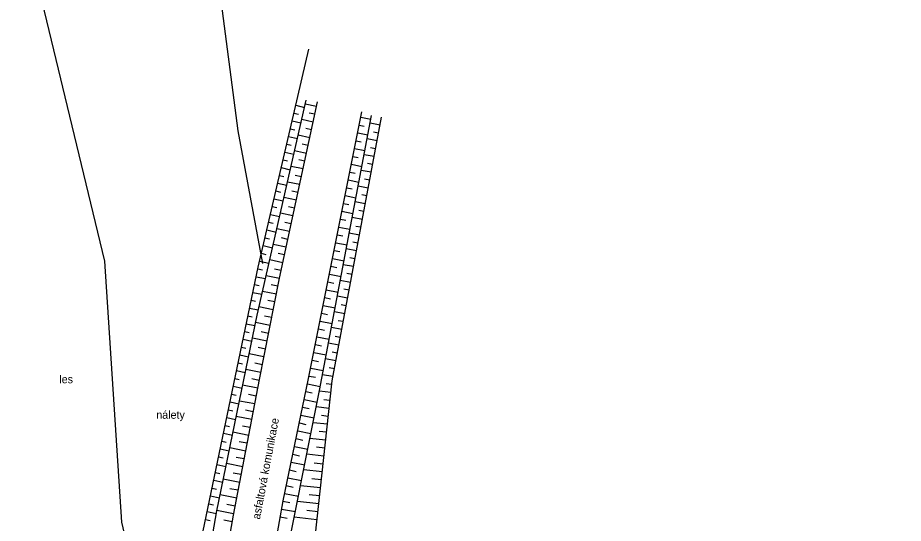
# Model space of a CAD drawing. Extents: x -762483 to -761175, y -1154655 to -1152452.
# Drawn here: x -761535.1 to -761452.1, y -1153499 to -1153451.6 of the extents above; entities that cross this region are included whole.
import ezdxf

# ---------------------------------------------------------------- set-up
doc = ezdxf.new("R2010")
doc.units = 0
for name, color, linetype in [('POMOC_POPIS', 7, 'Continuous'), ('ROZHRANÍ_PLOCH', 7, 'Continuous'), ('VÝŠKOPIS', 7, 'Continuous'), ('ZELEŇ', 7, 'Continuous')]:
    doc.layers.add(name, color=color, linetype=linetype)

msp = doc.modelspace()

# ---------------------------------------------------------------- linework, layer by layer
at = {"layer": 'ROZHRANÍ_PLOCH'}
for points in [[(-761473.21, -1153684.07), (-761469.46, -1153679.5), (-761466.97, -1153675.46), (-761465.27, -1153671.92), (-761464.53, -1153668.61), (-761464.73, -1153664.68), (-761466, -1153658.71), (-761468.55, -1153651.77), (-761473.7, -1153641.76), (-761483.81, -1153624.91), (-761489.13, -1153616.22), (-761501.02, -1153596.18), (-761505.16, -1153588.62), (-761508.76, -1153581.79), (-761515.86, -1153566.65), (-761518.43, -1153558.82), (-761520.62, -1153549.31), (-761520.92, -1153543.45), (-761519.67, -1153527.09), (-761518.4, -1153518.01), (-761514.9, -1153498.24), (-761512.46, -1153485.54), (-761510.57, -1153476.01), (-761507.02, -1153459.49)], [(-761452.11, -1153680.09), (-761455.06, -1153677.36), (-761457.46, -1153672.86), (-761459.23, -1153668.13), (-761461.75, -1153656.48), (-761464.72, -1153649.83), (-761470.08, -1153639.37), (-761481.24, -1153620.57), (-761493.92, -1153599.29), (-761502.78, -1153583.29), (-761511.19, -1153565.87), (-761514.81, -1153554.8), (-761515.74, -1153549.15), (-761516.42, -1153543.11), (-761515.79, -1153528.81), (-761514.01, -1153518.23), (-761510.25, -1153496.92), (-761507.85, -1153485.44), (-761506.02, -1153476.2), (-761502.85, -1153460.41)]]:
    msp.add_lwpolyline(points, dxfattribs=at)
at = {"layer": 'VÝŠKOPIS'}
for p, q in [((-761509.057, -1153459.81), (-761508.235, -1153460.002)), ((-761507.111, -1153459.915), (-761508.164, -1153459.689)), ((-761509.398, -1153461.271), (-761508.569, -1153461.464)), ((-761509.227, -1153460.541), (-761508.815, -1153460.637)), ((-761507.427, -1153461.382), (-761508.498, -1153461.152)), ((-761507.269, -1153460.649), (-761507.8, -1153460.534)), ((-761502.954, -1153460.928), (-761502.027, -1153461.114)), ((-761509.568, -1153462.002), (-761509.152, -1153462.098)), ((-761507.584, -1153462.115), (-761508.124, -1153461.999)), ((-761503.102, -1153461.663), (-761502.634, -1153461.757)), ((-761501.159, -1153461.669), (-761502.098, -1153461.493)), ((-761509.738, -1153462.732), (-761508.902, -1153462.926)), ((-761507.742, -1153462.848), (-761508.831, -1153462.614)), ((-761503.249, -1153462.399), (-761502.305, -1153462.588)), ((-761501.297, -1153462.407), (-761501.767, -1153462.319)), ((-761509.908, -1153463.462), (-761509.489, -1153463.56)), ((-761507.899, -1153463.582), (-761508.449, -1153463.464)), ((-761503.397, -1153463.134), (-761502.921, -1153463.23)), ((-761501.435, -1153463.144), (-761502.377, -1153462.967)), ((-761501.573, -1153463.881), (-761502.044, -1153463.793)), ((-761510.078, -1153464.193), (-761509.236, -1153464.389)), ((-761508.057, -1153464.315), (-761509.165, -1153464.077)), ((-761503.692, -1153464.605), (-761503.207, -1153464.702)), ((-761503.545, -1153463.869), (-761502.583, -1153464.062)), ((-761501.711, -1153464.618), (-761502.655, -1153464.441)), ((-761510.248, -1153464.923), (-761509.825, -1153465.022)), ((-761508.214, -1153465.048), (-761508.773, -1153464.928)), ((-761503.84, -1153465.34), (-761502.862, -1153465.537)), ((-761501.849, -1153465.355), (-761502.321, -1153465.267)), ((-761510.418, -1153465.654), (-761509.57, -1153465.851)), ((-761508.372, -1153465.781), (-761509.498, -1153465.539)), ((-761503.987, -1153466.075), (-761503.494, -1153466.175)), ((-761501.987, -1153466.093), (-761502.933, -1153465.915)), ((-761510.758, -1153467.115), (-761509.903, -1153467.314)), ((-761510.588, -1153466.384), (-761510.162, -1153466.483)), ((-761508.687, -1153467.248), (-761509.832, -1153467.002)), ((-761508.53, -1153466.515), (-761509.097, -1153466.393)), ((-761504.135, -1153466.811), (-761503.14, -1153467.011)), ((-761502.125, -1153466.83), (-761502.599, -1153466.741)), ((-761510.928, -1153467.845), (-761510.499, -1153467.945)), ((-761508.845, -1153467.981), (-761509.422, -1153467.857)), ((-761504.283, -1153467.546), (-761503.781, -1153467.647)), ((-761502.263, -1153467.567), (-761503.211, -1153467.389)), ((-761511.099, -1153468.576), (-761510.237, -1153468.776)), ((-761509.002, -1153468.714), (-761510.165, -1153468.464)), ((-761504.43, -1153468.281), (-761503.418, -1153468.485)), ((-761502.401, -1153468.304), (-761502.876, -1153468.215)), ((-761511.269, -1153469.306), (-761510.836, -1153469.407)), ((-761509.16, -1153469.448), (-761509.746, -1153469.322)), ((-761504.578, -1153469.017), (-761504.068, -1153469.119)), ((-761502.539, -1153469.041), (-761503.49, -1153468.863)), ((-761511.439, -1153470.037), (-761510.57, -1153470.239)), ((-761509.317, -1153470.181), (-761510.499, -1153469.927)), ((-761504.726, -1153469.752), (-761503.696, -1153469.959)), ((-761502.815, -1153470.516), (-761503.768, -1153470.337)), ((-761502.677, -1153469.778), (-761503.153, -1153469.689)), ((-761511.609, -1153470.767), (-761511.173, -1153470.868)), ((-761509.475, -1153470.914), (-761510.07, -1153470.786)), ((-761505.021, -1153471.223), (-761503.975, -1153471.433)), ((-761504.873, -1153470.487), (-761504.354, -1153470.592)), ((-761502.953, -1153471.253), (-761503.43, -1153471.164)), ((-761511.779, -1153471.497), (-761510.904, -1153471.701)), ((-761509.633, -1153471.647), (-761510.833, -1153471.39)), ((-761505.168, -1153471.958), (-761504.641, -1153472.064)), ((-761503.092, -1153471.99), (-761504.046, -1153471.811)), ((-761511.949, -1153472.228), (-761511.51, -1153472.33)), ((-761509.948, -1153473.114), (-761511.166, -1153472.852)), ((-761509.79, -1153472.381), (-761510.395, -1153472.251)), ((-761505.316, -1153472.693), (-761504.253, -1153472.907)), ((-761503.23, -1153472.727), (-761503.707, -1153472.638)), ((-761512.289, -1153473.689), (-761511.847, -1153473.792)), ((-761512.119, -1153472.958), (-761511.237, -1153473.164)), ((-761510.105, -1153473.847), (-761510.719, -1153473.715)), ((-761505.464, -1153473.429), (-761504.928, -1153473.536)), ((-761503.368, -1153473.464), (-761504.324, -1153473.285)), ((-761512.459, -1153474.419), (-761511.571, -1153474.626)), ((-761510.263, -1153474.58), (-761511.5, -1153474.315)), ((-761505.611, -1153474.164), (-761504.531, -1153474.381)), ((-761503.506, -1153474.202), (-761503.985, -1153474.112)), ((-761512.625, -1153475.151), (-761512.179, -1153475.243)), ((-761510.42, -1153475.314), (-761511.043, -1153475.18)), ((-761505.759, -1153474.899), (-761505.215, -1153475.009)), ((-761503.644, -1153474.939), (-761504.602, -1153474.759)), ((-761512.778, -1153475.885), (-761511.899, -1153476.067)), ((-761510.577, -1153476.047), (-761511.838, -1153475.797)), ((-761505.907, -1153475.635), (-761504.809, -1153475.855)), ((-761503.92, -1153476.413), (-761504.881, -1153476.233)), ((-761503.782, -1153475.676), (-761504.262, -1153475.586)), ((-761512.931, -1153476.619), (-761512.498, -1153476.709)), ((-761510.723, -1153476.783), (-761511.364, -1153476.656)), ((-761506.054, -1153476.37), (-761505.501, -1153476.48)), ((-761504.058, -1153477.15), (-761504.539, -1153477.06)), ((-761513.083, -1153477.354), (-761512.233, -1153477.53)), ((-761510.869, -1153477.518), (-761512.171, -1153477.26)), ((-761506.345, -1153477.842), (-761505.786, -1153477.952)), ((-761506.199, -1153477.106), (-761505.087, -1153477.326)), ((-761504.196, -1153477.887), (-761505.159, -1153477.707)), ((-761513.236, -1153478.088), (-761512.818, -1153478.175)), ((-761511.161, -1153478.99), (-761512.505, -1153478.723)), ((-761511.015, -1153478.254), (-761511.677, -1153478.123)), ((-761506.491, -1153478.577), (-761505.365, -1153478.8)), ((-761504.334, -1153478.625), (-761504.816, -1153478.534)), ((-761513.541, -1153479.557), (-761513.135, -1153479.641)), ((-761513.388, -1153478.822), (-761512.567, -1153478.993)), ((-761506.637, -1153479.313), (-761506.07, -1153479.425)), ((-761504.472, -1153479.362), (-761505.437, -1153479.181)), ((-761513.693, -1153480.291), (-761512.88, -1153480.46)), ((-761511.453, -1153480.461), (-761512.824, -1153480.189)), ((-761511.307, -1153479.725), (-761511.989, -1153479.59)), ((-761506.782, -1153480.049), (-761505.643, -1153480.274)), ((-761504.61, -1153480.099), (-761505.093, -1153480.009)), ((-761513.846, -1153481.025), (-761513.439, -1153481.11)), ((-761511.599, -1153481.197), (-761512.287, -1153481.06)), ((-761506.928, -1153480.784), (-761506.355, -1153480.898)), ((-761504.748, -1153480.836), (-761505.715, -1153480.655)), ((-761513.999, -1153481.759), (-761513.182, -1153481.929)), ((-761511.745, -1153481.933), (-761513.127, -1153481.658)), ((-761507.074, -1153481.52), (-761505.922, -1153481.748)), ((-761504.886, -1153481.573), (-761505.37, -1153481.483)), ((-761514.151, -1153482.494), (-761513.742, -1153482.579)), ((-761511.89, -1153482.668), (-761512.584, -1153482.531)), ((-761507.219, -1153482.256), (-761506.64, -1153482.371)), ((-761505.025, -1153482.311), (-761505.994, -1153482.129)), ((-761514.304, -1153483.228), (-761513.485, -1153483.398)), ((-761512.036, -1153483.404), (-761513.429, -1153483.128)), ((-761507.365, -1153482.992), (-761506.2, -1153483.222)), ((-761505.301, -1153483.785), (-761506.272, -1153483.603)), ((-761505.163, -1153483.048), (-761505.648, -1153482.957)), ((-761514.456, -1153483.962), (-761514.046, -1153484.048)), ((-761512.182, -1153484.14), (-761512.881, -1153484.001)), ((-761507.656, -1153484.463), (-761506.478, -1153484.696)), ((-761507.511, -1153483.727), (-761506.925, -1153483.843)), ((-761505.439, -1153484.522), (-761505.925, -1153484.431)), ((-761514.609, -1153484.697), (-761513.788, -1153484.867)), ((-761512.328, -1153484.875), (-761513.732, -1153484.597)), ((-761507.802, -1153485.199), (-761507.21, -1153485.316)), ((-761505.577, -1153485.259), (-761506.55, -1153485.077)), ((-761514.914, -1153486.165), (-761514.09, -1153486.336)), ((-761514.761, -1153485.431), (-761514.35, -1153485.516)), ((-761512.615, -1153486.347), (-761514.036, -1153486.074)), ((-761512.474, -1153485.611), (-761513.179, -1153485.475)), ((-761507.953, -1153485.933), (-761506.759, -1153486.183)), ((-761505.688, -1153486), (-761506.196, -1153485.945)), ((-761515.066, -1153486.9), (-761514.654, -1153486.985)), ((-761512.757, -1153487.084), (-761513.472, -1153486.947)), ((-761508.107, -1153486.667), (-761507.504, -1153486.793)), ((-761505.769, -1153486.746), (-761506.844, -1153486.629)), ((-761515.219, -1153487.634), (-761514.393, -1153487.806)), ((-761512.898, -1153487.821), (-761514.339, -1153487.544)), ((-761508.26, -1153487.402), (-761507.048, -1153487.655)), ((-761505.851, -1153487.492), (-761506.421, -1153487.429)), ((-761515.372, -1153488.368), (-761514.958, -1153488.454)), ((-761513.04, -1153488.557), (-761513.765, -1153488.418)), ((-761508.414, -1153488.136), (-761507.804, -1153488.263)), ((-761505.932, -1153488.237), (-761507.138, -1153488.106)), ((-761515.524, -1153489.103), (-761514.696, -1153489.275)), ((-761513.181, -1153489.294), (-761514.642, -1153489.013)), ((-761508.567, -1153488.87), (-761507.341, -1153489.126)), ((-761506.013, -1153488.983), (-761506.649, -1153488.913)), ((-761515.677, -1153489.837), (-761515.262, -1153489.923)), ((-761513.323, -1153490.03), (-761514.058, -1153489.889)), ((-761508.874, -1153490.338), (-761507.634, -1153490.597)), ((-761508.721, -1153489.604), (-761508.104, -1153489.733)), ((-761506.095, -1153489.728), (-761507.432, -1153489.583)), ((-761515.829, -1153490.571), (-761514.998, -1153490.744)), ((-761513.464, -1153490.767), (-761514.944, -1153490.482)), ((-761509.027, -1153491.072), (-761508.404, -1153491.203)), ((-761506.257, -1153491.219), (-761507.726, -1153491.059)), ((-761506.176, -1153490.474), (-761506.878, -1153490.397)), ((-761515.982, -1153491.306), (-761515.566, -1153491.392)), ((-761513.747, -1153492.24), (-761515.247, -1153491.952)), ((-761513.606, -1153491.503), (-761514.351, -1153491.36)), ((-761509.181, -1153491.806), (-761507.928, -1153492.068)), ((-761506.338, -1153491.965), (-761507.106, -1153491.881)), ((-761516.287, -1153492.774), (-761515.87, -1153492.861)), ((-761516.134, -1153492.04), (-761515.301, -1153492.213)), ((-761513.889, -1153492.976), (-761514.644, -1153492.831)), ((-761509.334, -1153492.54), (-761508.704, -1153492.672)), ((-761506.42, -1153492.711), (-761508.021, -1153492.536)), ((-761516.44, -1153493.509), (-761515.604, -1153493.682)), ((-761514.03, -1153493.713), (-761515.55, -1153493.421)), ((-761509.488, -1153493.275), (-761508.221, -1153493.54)), ((-761506.501, -1153493.456), (-761507.334, -1153493.365)), ((-761516.592, -1153494.243), (-761516.173, -1153494.33)), ((-761514.172, -1153494.449), (-761514.936, -1153494.302)), ((-761509.641, -1153494.009), (-761509.004, -1153494.142)), ((-761506.582, -1153494.202), (-761508.315, -1153494.013)), ((-761516.745, -1153494.977), (-761515.906, -1153495.151)), ((-761514.313, -1153495.186), (-761515.852, -1153494.89)), ((-761509.795, -1153494.743), (-761508.514, -1153495.011)), ((-761506.663, -1153494.947), (-761507.563, -1153494.849)), ((-761516.897, -1153495.712), (-761516.477, -1153495.799)), ((-761514.455, -1153495.922), (-761515.229, -1153495.774)), ((-761509.948, -1153495.477), (-761509.304, -1153495.612)), ((-761506.745, -1153495.693), (-761508.609, -1153495.49)), ((-761517.05, -1153496.446), (-761516.209, -1153496.621)), ((-761514.596, -1153496.659), (-761516.155, -1153496.359)), ((-761510.254, -1153496.945), (-761509.6, -1153497.061)), ((-761510.102, -1153496.211), (-761508.807, -1153496.482)), ((-761506.907, -1153497.184), (-761508.903, -1153496.967)), ((-761506.826, -1153496.439), (-761507.791, -1153496.333)), ((-761517.202, -1153497.18), (-761516.781, -1153497.268)), ((-761514.879, -1153498.132), (-761516.458, -1153497.829)), ((-761514.738, -1153497.395), (-761515.522, -1153497.245)), ((-761510.385, -1153497.684), (-761509.092, -1153497.912)), ((-761506.989, -1153497.93), (-761508.02, -1153497.817)), ((-761517.507, -1153498.649), (-761517.07, -1153498.74)), ((-761517.355, -1153497.914), (-761516.504, -1153498.091)), ((-761510.515, -1153498.423), (-761509.877, -1153498.535)), ((-761507.07, -1153498.675), (-761509.198, -1153498.443)), ((-761515.012, -1153498.87), (-761515.801, -1153498.73))]:
    msp.add_line(p, q, dxfattribs=at)
for points in [[(-761522.41, -1153530.52), (-761520.68, -1153517.87), (-761517.73, -1153499.72), (-761512.59, -1153474.98), (-761507.83, -1153454.54)], [(-761522.41, -1153530.52), (-761521.38, -1153528.25), (-761519.93, -1153517.76), (-761516.46, -1153497.84), (-761512.68, -1153479.49), (-761508.08, -1153459.32)], [(-761510.51, -1153505.03), (-761506.83, -1153486.56), (-761501.96, -1153460.76)]]:
    msp.add_lwpolyline(points, dxfattribs=at)
at = {"layer": 'ZELEŇ'}
for points in [[(-761512.13, -1153474.66), (-761514.45, -1153462.2), (-761517.85, -1153436.07), (-761517.18, -1153429.66)], [(-761522.41, -1153530.52), (-761521.16, -1153516.7), (-761525.36, -1153498.92), (-761526.95, -1153474.42), (-761535, -1153440.98), (-761535.12, -1153438.71)], [(-761507.72, -1153504.64), (-761505.65, -1153485.65), (-761501.02, -1153460.93)]]:
    msp.add_lwpolyline(points, dxfattribs=at)

# ---------------------------------------------------------------- texts
at = {"layer": 'POMOC_POPIS'}
msp.add_text('asfaltová komunikace', height=0.75, rotation=79.2611, dxfattribs=at).set_placement((-761512.42, -1153498.69))
at = {"layer": 'ZELEŇ'}
for s, p in [('les', (-761531.22, -1153485.88)), ('nálety', (-761522.13, -1153489.21))]:
    msp.add_text(s, height=0.75, dxfattribs=at).set_placement(p)

doc.saveas('drawing.dxf')
